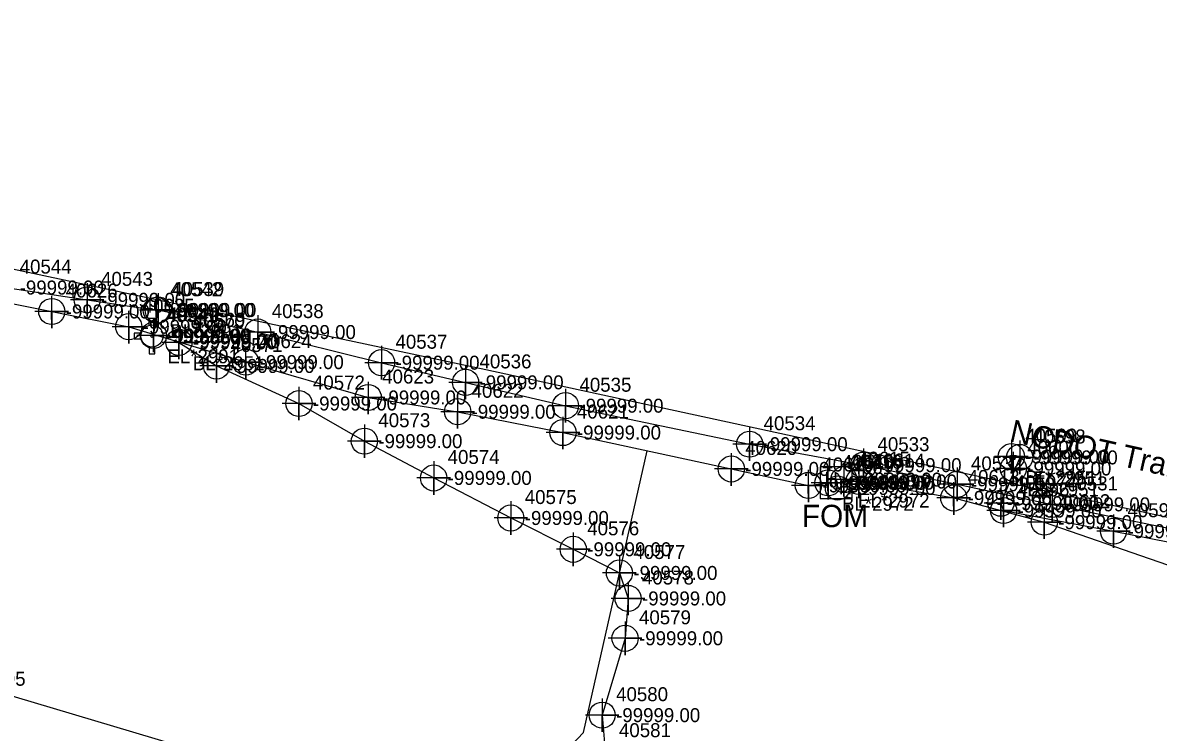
# Model space of a CAD drawing. Extents: x 2083698 to 2094313, y 743246 to 752873.
# Drawn here: x 2091095.5 to 2091298.8, y 744345.3 to 744472.3 of the extents above; entities that cross this region are included whole.
import ezdxf

# ---------------------------------------------------------------- set-up
doc = ezdxf.new("R2010")
doc.units = 0
for name, color, linetype in [('COGO Default Parcel', 7, 'Continuous'), ('COGO Default Point Number', 7, 'Continuous'), ('Exist Property Iron Pin CELL', 7, 'Continuous'), ('Exist Property Iron Pin Cogo Elevation', 7, 'Continuous'), ('Exist Property Iron Pin Cogo Number', 7, 'Continuous'), ('Exist Property Iron Pin Leader', 7, 'Continuous'), ('Exist Property Iron Pin Text', 7, 'Continuous'), ('Exist Property Line', 7, 'Continuous'), ('Exist Property Monument Leader', 7, 'Continuous'), ('Exist Property Monument Text', 7, 'Continuous'), ('Exist Right of Way Easement Line Leader', 7, 'Continuous'), ('Exist Right of Way Easement Line Text', 7, 'Continuous'), ('Exist Right of Way Line', 7, 'Continuous'), ('Exist Right of Way Line Leader', 7, 'Continuous'), ('Exist Right of Way Line Text', 7, 'Continuous'), ('Exist Right of Way Width CELL', 7, 'Continuous'), ('Exist Utilities Other Located Object CELL', 7, 'Continuous'), ('Exist Utilities Other Located Object Text', 7, 'Continuous'), ('Exist Utilities Power Joint Use Telephone Cogo Elevation', 7, 'Continuous'), ('Exist Utilities Power Joint Use Telephone Cogo Number', 7, 'Continuous'), ('Exist Utilities Power UG Cable SUE LOS B', 7, 'Continuous'), ('Exist Utilities Power UG Cable SUE LOS B Text', 7, 'Continuous'), ('Exist Utilities Telephone UG Conduit SUE LOS B', 7, 'Continuous'), ('Exist Utilities Telephone UG Conduit SUE LOS C', 7, 'Continuous'), ('Exist Utilities TV UG Cable SUE LOS C', 7, 'Continuous'), ('Exist Utilities Water UG Line SUE LOS B', 7, 'Continuous'), ('Raster_Level_1', 7, 'Continuous'), ('Scratch_Level_0', 7, 'Continuous'), ('Scratch_Level_2', 7, 'Continuous'), ('Scratch_Level_3', 7, 'Continuous')]:
    doc.layers.add(name, color=color, linetype=linetype)

msp = doc.modelspace()

# ---------------------------------------------------------------- linework, layer by layer
at = {"layer": 'COGO Default Point Number'}
for points in [[(2091107.01, 744425.67), (2091107.01, 744419.67), (2091107.01, 744422.67), (2091110.01, 744422.67), (2091104.01, 744422.67)], [(2091119.4, 744423.81), (2091119.4, 744417.81), (2091119.4, 744420.81), (2091122.4, 744420.81), (2091116.4, 744420.81)], [(2091119.75, 744423.85), (2091119.75, 744417.85), (2091119.75, 744420.85), (2091122.75, 744420.85), (2091116.75, 744420.85)], [(2091137.57, 744419.9), (2091137.57, 744413.9), (2091137.57, 744416.9), (2091140.57, 744416.9), (2091134.57, 744416.9)], [(2091118.88, 744419.31), (2091118.88, 744413.31), (2091118.88, 744416.31), (2091121.88, 744416.31), (2091115.88, 744416.31)], [(2091159.73, 744414.42), (2091159.73, 744408.42), (2091159.73, 744411.42), (2091162.73, 744411.42), (2091156.73, 744411.42)], [(2091174.78, 744410.9), (2091174.78, 744404.9), (2091174.78, 744407.9), (2091177.78, 744407.9), (2091171.78, 744407.9)], [(2091192.68, 744406.72), (2091192.68, 744400.72), (2091192.68, 744403.72), (2091195.68, 744403.72), (2091189.68, 744403.72)], [(2091225.65, 744399.83), (2091225.65, 744393.83), (2091225.65, 744396.83), (2091228.65, 744396.83), (2091222.65, 744396.83)], [(2091246.05, 744396.08), (2091246.05, 744390.08), (2091246.05, 744393.08), (2091249.05, 744393.08), (2091243.05, 744393.08)], [(2091262.79, 744392.65), (2091262.79, 744386.65), (2091262.79, 744389.65), (2091265.79, 744389.65), (2091259.79, 744389.65)], [(2091279.81, 744389.06), (2091279.81, 744383.06), (2091279.81, 744386.06), (2091282.81, 744386.06), (2091276.81, 744386.06)]]:
    msp.add_lwpolyline(points, dxfattribs=at)
for centre in [(2091107.01, 744422.67), (2091119.4, 744420.81), (2091119.75, 744420.85), (2091118.88, 744416.31), (2091137.57, 744416.9), (2091159.73, 744411.42), (2091174.78, 744407.9), (2091192.68, 744403.72), (2091225.65, 744396.83), (2091246.05, 744393.08), (2091262.79, 744389.65), (2091279.81, 744386.06)]:
    msp.add_circle(centre, 2.34, dxfattribs=at)
at = {"layer": 'Exist Property Iron Pin CELL'}
for p, q in [((2091238.28, 744392.8), (2091238.28, 744387.08)), ((2091244, 744392.8), (2091238.28, 744392.8)), ((2091244, 744387.08), (2091244, 744392.8)), ((2091241.14, 744389.94), (2091241.14, 744389.94)), ((2091238.28, 744387.08), (2091244, 744387.08))]:
    msp.add_line(p, q, dxfattribs=at)
at = {"layer": 'Exist Property Iron Pin Text'}
for points in [[(2091123.44, 744418.06), (2091123.44, 744412.06), (2091123.44, 744415.06), (2091126.44, 744415.06), (2091120.44, 744415.06)], [(2091130.19, 744413.83), (2091130.19, 744407.83), (2091130.19, 744410.83), (2091133.19, 744410.83), (2091127.19, 744410.83)], [(2091144.95, 744407.11), (2091144.95, 744401.11), (2091144.95, 744404.11), (2091147.95, 744404.11), (2091141.95, 744404.11)], [(2091156.66, 744400.37), (2091156.66, 744394.37), (2091156.66, 744397.37), (2091159.66, 744397.37), (2091153.66, 744397.37)], [(2091272.52, 744397.61), (2091272.52, 744391.61), (2091272.52, 744394.61), (2091275.52, 744394.61), (2091269.52, 744394.61)], [(2091274.01, 744397.46), (2091274.01, 744391.46), (2091274.01, 744394.46), (2091277.01, 744394.46), (2091271.01, 744394.46)], [(2091272.87, 744395.49), (2091272.87, 744389.49), (2091272.87, 744392.49), (2091275.87, 744392.49), (2091269.87, 744392.49)], [(2091169.07, 744393.79), (2091169.07, 744387.79), (2091169.07, 744390.79), (2091172.07, 744390.79), (2091166.07, 744390.79)], [(2091270.65, 744389.26), (2091270.65, 744383.26), (2091270.65, 744386.26), (2091273.65, 744386.26), (2091267.65, 744386.26)], [(2091271.12, 744387.96), (2091271.12, 744381.96), (2091271.12, 744384.96), (2091274.12, 744384.96), (2091268.12, 744384.96)], [(2091182.88, 744386.62), (2091182.88, 744380.62), (2091182.88, 744383.62), (2091185.88, 744383.62), (2091179.88, 744383.62)], [(2091290.81, 744384.26), (2091290.81, 744378.26), (2091290.81, 744381.26), (2091293.81, 744381.26), (2091287.81, 744381.26)], [(2091194.07, 744381.02), (2091194.07, 744375.02), (2091194.07, 744378.02), (2091197.07, 744378.02), (2091191.07, 744378.02)], [(2091202.33, 744376.78), (2091202.33, 744370.78), (2091202.33, 744373.78), (2091205.33, 744373.78), (2091199.33, 744373.78)], [(2091203.88, 744372.22), (2091203.88, 744366.22), (2091203.88, 744369.22), (2091206.88, 744369.22), (2091200.88, 744369.22)], [(2091203.34, 744365.09), (2091203.34, 744359.09), (2091203.34, 744362.09), (2091206.34, 744362.09), (2091200.34, 744362.09)], [(2091199.24, 744351.33), (2091199.24, 744345.33), (2091199.24, 744348.33), (2091202.24, 744348.33), (2091196.24, 744348.33)]]:
    msp.add_lwpolyline(points, dxfattribs=at)
for centre in [(2091123.44, 744415.06), (2091130.19, 744410.83), (2091144.95, 744404.11), (2091156.66, 744397.37), (2091272.52, 744394.61), (2091274.01, 744394.46), (2091169.07, 744390.79), (2091272.87, 744392.49), (2091270.65, 744386.26), (2091271.12, 744384.96), (2091182.88, 744383.62), (2091290.81, 744381.26), (2091194.07, 744378.02), (2091202.33, 744373.78), (2091203.88, 744369.22), (2091203.34, 744362.09), (2091199.24, 744348.33)]:
    msp.add_circle(centre, 2.34, dxfattribs=at)
at = {"layer": 'Exist Right of Way Line Text'}
for points in [[(2091100.63, 744423.4), (2091100.67, 744417.58), (2091100.65, 744420.58), (2091103.67, 744420.58), (2091097.67, 744420.58)], [(2091114.43, 744420.67), (2091114.47, 744414.86), (2091114.45, 744417.86), (2091117.47, 744417.86), (2091111.47, 744417.86)], [(2091135.38, 744414.33), (2091135.41, 744408.52), (2091135.4, 744411.52), (2091138.41, 744411.52), (2091132.41, 744411.52)], [(2091157.32, 744408), (2091157.35, 744402.19), (2091157.33, 744405.19), (2091160.35, 744405.19), (2091154.35, 744405.19)], [(2091173.33, 744405.45), (2091173.36, 744399.64), (2091173.34, 744402.64), (2091176.36, 744402.64), (2091170.36, 744402.64)], [(2091192.19, 744401.72), (2091192.22, 744395.91), (2091192.2, 744398.91), (2091195.22, 744398.91), (2091189.22, 744398.91)], [(2091222.34, 744395.21), (2091222.37, 744389.4), (2091222.36, 744392.4), (2091225.37, 744392.4), (2091219.37, 744392.4)], [(2091242.51, 744393.31), (2091242.54, 744387.49), (2091242.52, 744390.49), (2091245.54, 744390.49), (2091239.54, 744390.49)], [(2091245.18, 744392.96), (2091245.22, 744387.15), (2091245.2, 744390.15), (2091248.22, 744390.15), (2091242.22, 744390.15)], [(2091236.14, 744392.26), (2091236.17, 744386.45), (2091236.15, 744389.45), (2091239.17, 744389.45), (2091233.17, 744389.45)], [(2091239.65, 744392.73), (2091239.69, 744386.91), (2091239.67, 744389.91), (2091242.69, 744389.91), (2091236.69, 744389.91)], [(2091262.17, 744390.03), (2091262.2, 744384.21), (2091262.18, 744387.21), (2091265.2, 744387.21), (2091259.2, 744387.21)], [(2091278.39, 744385.69), (2091278.42, 744379.87), (2091278.41, 744382.87), (2091281.42, 744382.87), (2091275.42, 744382.87)]]:
    msp.add_lwpolyline(points, dxfattribs=at)
for centre in [(2091100.67, 744420.58), (2091114.47, 744417.86), (2091135.41, 744411.52), (2091157.35, 744405.19), (2091173.36, 744402.64), (2091192.22, 744398.91), (2091222.37, 744392.4), (2091236.17, 744389.45), (2091239.69, 744389.91), (2091242.54, 744390.49), (2091245.22, 744390.15), (2091262.2, 744387.21), (2091278.42, 744382.87)]:
    msp.add_circle(centre, 2.34, dxfattribs=at)
at = {"layer": 'Exist Utilities Other Located Object CELL'}
for radius in [2.18, 0.24]:
    msp.add_circle((2091241.39, 744388.99), radius, dxfattribs=at)
at = {"layer": 'Exist Utilities Power UG Cable SUE LOS B'}
msp.add_line((2091272.52, 744394.61), (2091272.87, 744392.49), dxfattribs=at)
for points in [[(2091123.44, 744415.06), (2091130.19, 744410.83), (2091144.95, 744404.11), (2091156.66, 744397.37), (2091169.07, 744390.79), (2091182.88, 744383.62), (2091194.07, 744378.02), (2091202.33, 744373.78), (2091203.88, 744369.22), (2091203.34, 744362.09), (2091199.24, 744348.33), (2091199.75, 744341.89), (2091203.94, 744334.56), (2091208.76, 744334.42), (2091211.38, 744336.87)], [(2091274.01, 744394.46), (2091270.65, 744386.26), (2091271.12, 744384.96), (2091290.81, 744381.26), (2091304.17, 744378.63), (2091324.7, 744374.67), (2091337.06, 744369.57), (2091348.22, 744363.92), (2091350.33, 744362.88)]]:
    msp.add_lwpolyline(points, dxfattribs=at)
at = {"layer": 'Exist Utilities Telephone UG Conduit SUE LOS B'}
for points in [[(2090890.56, 744469.77), (2090897.36, 744470.03), (2090919.19, 744460.85), (2090939.78, 744455.97), (2090957.49, 744454.33), (2090977.44, 744448.69), (2090996.96, 744442.97), (2091015.78, 744439.38), (2091033.71, 744434.32), (2091057.15, 744429.17), (2091077.11, 744425.28), (2091100.67, 744420.58), (2091114.47, 744417.86), (2091135.41, 744411.52), (2091157.35, 744405.19), (2091173.36, 744402.64), (2091192.22, 744398.91), (2091222.37, 744392.4), (2091236.17, 744389.45), (2091239.69, 744389.91)], [(2090806.91, 744430.84), (2090828.12, 744425.56), (2090875.81, 744412.95), (2090912.62, 744403.8), (2090953.84, 744392.46), (2090996.45, 744380.46), (2091034.29, 744369.44), (2091083.26, 744354.84), (2091136.72, 744338.88), (2091178.24, 744327.59), (2091220.24, 744315.64), (2091261.35, 744302.25), (2091279.18, 744292.69), (2091315.02, 744278.76)], [(2091242.54, 744390.49), (2091245.22, 744390.15), (2091262.2, 744387.21), (2091278.42, 744382.87), (2091303.56, 744374.19), (2091323.58, 744368.52), (2091346.95, 744365.26), (2091375.52, 744357.7), (2091401.28, 744349.84), (2091424.1, 744344.64), (2091445.92, 744340.4), (2091465.61, 744335.98), (2091473.85, 744334.83), (2091473.86, 744334.82), (2091479.86, 744333.66)]]:
    msp.add_lwpolyline(points, dxfattribs=at)
at = {"layer": 'Exist Utilities Telephone UG Conduit SUE LOS C'}
msp.add_lwpolyline([(2091183.95, 744332.62), (2091195.91, 744345.2), (2091207.3, 744395.65)], dxfattribs=at)
at = {"layer": 'Exist Utilities TV UG Cable SUE LOS C'}
msp.add_lwpolyline([(2091054.67, 744436.34), (2091073.65, 744432.47), (2091178.42, 744410.18), (2091400.3, 744362.19), (2091479.76, 744342.26), (2091533.68, 744324.76), (2091743.8, 744269.35), (2091786.22, 744260.43)], dxfattribs=at)
at = {"layer": 'Exist Utilities Water UG Line SUE LOS B'}
for points in [[(2090757, 744489.94), (2090781.29, 744488.85), (2090797.98, 744487.59), (2090827.47, 744482.42), (2090838.65, 744479.65), (2090852.58, 744478.98), (2090873.77, 744477.12), (2090883.51, 744476.24), (2090899.92, 744472.35), (2090921.56, 744466.76), (2090941.24, 744461.84), (2090958.11, 744457.6), (2090978.69, 744451.85), (2090998.25, 744447.07), (2091015.68, 744441.91), (2091033.15, 744437.09), (2091043.48, 744435.09), (2091058.27, 744432.2), (2091077.37, 744428.05), (2091092.43, 744424.87), (2091107.01, 744422.67), (2091119.4, 744420.81)], [(2091118.88, 744416.31), (2091119.75, 744420.85)], [(2091119.75, 744420.85), (2091137.57, 744416.9), (2091159.73, 744411.42), (2091174.78, 744407.9), (2091192.68, 744403.72), (2091225.65, 744396.83), (2091246.05, 744393.08), (2091262.79, 744389.65), (2091279.81, 744386.06), (2091324.78, 744376.93), (2091324.75, 744376.92), (2091377.96, 744364.84), (2091402.77, 744359.19), (2091425.76, 744353.62), (2091447.37, 744348.1), (2091466.41, 744343.18), (2091483.9, 744339.28), (2091501.85, 744335.1), (2091516.05, 744331.54), (2091527.86, 744328.96), (2091537.96, 744326.53)]]:
    msp.add_lwpolyline(points, dxfattribs=at)
at = {"layer": 'Raster_Level_1'}
msp.add_line((2091118.62, 744416.19), (2091118.62, 744416.19), dxfattribs=at)
for points in [[(2091118.11, 744418.11), (2091118.11, 744419.39), (2091119.14, 744419.39), (2091119.14, 744418.08)], [(2091116.71, 744416.71), (2091115.43, 744416.71), (2091115.43, 744415.68), (2091116.71, 744415.68)], [(2091118.11, 744414.28), (2091118.11, 744412.99), (2091119.14, 744412.99), (2091119.14, 744414.31)]]:
    msp.add_lwpolyline(points, dxfattribs=at)
for radius in [1.98, 0.243]:
    msp.add_circle((2091118.62, 744416.19), radius, dxfattribs=at)

# ---------------------------------------------------------------- texts
at = {"layer": 'COGO Default Parcel'}
msp.add_text('40617', height=2.5, dxfattribs=at).set_placement((2091243.89, 744391.49))
at = {"layer": 'Exist Property Iron Pin CELL'}
for p in [(2091239.06, 744389.35), (2091241.63, 744387.88)]:
    msp.add_text('H', height=2.5, dxfattribs=at).set_placement(p)
at = {"layer": 'Exist Property Iron Pin Cogo Elevation'}
msp.add_text('-99999.00', height=2.5, dxfattribs=at).set_placement((2091243.64, 744388.69))
at = {"layer": 'Exist Property Iron Pin Cogo Number'}
msp.add_text('40616', height=2.5, dxfattribs=at).set_placement((2091243.64, 744392.44))
at = {"layer": 'Exist Property Iron Pin Leader'}
for s, p in [('40570', (2091125.94, 744417.56)), ('40571', (2091132.69, 744413.33)), ('40572', (2091147.45, 744406.61)), ('40573', (2091159.16, 744399.87)), ('40599', (2091275.02, 744397.11)), ('40598', (2091276.51, 744396.96)), ('40600', (2091275.37, 744394.99)), ('40574', (2091171.57, 744393.29)), ('40597', (2091273.15, 744388.76)), ('40596', (2091273.62, 744387.46)), ('40575', (2091185.38, 744386.12)), ('40595', (2091293.31, 744383.76)), ('40576', (2091196.57, 744380.52)), ('40577', (2091204.83, 744376.28)), ('40578', (2091206.38, 744371.72)), ('40579', (2091205.84, 744364.59)), ('40580', (2091201.74, 744350.83)), ('40581', (2091202.25, 744344.39))]:
    msp.add_text(s, height=2.5, dxfattribs=at).set_placement(p)
at = {"layer": 'Exist Property Line'}
for p in [(2091094.93, 744423.62), (2091109.51, 744421.42), (2091121.9, 744419.56), (2091122.25, 744419.6), (2091121.38, 744415.06), (2091140.07, 744415.65), (2091162.23, 744410.17), (2091177.28, 744406.65), (2091195.18, 744402.47), (2091228.15, 744395.58), (2091248.55, 744391.83), (2091265.29, 744388.4), (2091282.31, 744384.81)]:
    msp.add_text('-99999.00', height=2.5, dxfattribs=at).set_placement(p)
at = {"layer": 'Exist Property Monument Leader'}
for s, p in [('BL*2951', (2091125.94, 744410.06)), ('BL*2951', (2091275.02, 744389.61)), ('EL*2951', (2091276.51, 744389.46)), ('EL*2951', (2091275.37, 744387.49))]:
    msp.add_text(s, height=2.5, dxfattribs=at).set_placement(p)
at = {"layer": 'Exist Property Monument Text'}
for p in [(2091125.94, 744413.81), (2091132.69, 744409.58), (2091147.45, 744402.86), (2091159.16, 744396.12), (2091275.02, 744393.36), (2091276.51, 744393.21), (2091275.37, 744391.24), (2091171.57, 744389.54), (2091273.15, 744385.01), (2091185.38, 744382.37), (2091273.62, 744383.71), (2091293.31, 744380.01), (2091196.57, 744376.77), (2091204.83, 744372.53), (2091206.38, 744367.97), (2091205.84, 744360.84), (2091201.74, 744347.08)]:
    msp.add_text('-99999.00', height=2.5, dxfattribs=at).set_placement(p)
at = {"layer": 'Exist Right of Way Easement Line Leader'}
msp.add_text('-99999.00', height=2.5, dxfattribs=at).set_placement((2091121.12, 744414.94))
at = {"layer": 'Exist Right of Way Easement Line Text'}
msp.add_text('40541', height=2.5, dxfattribs=at).set_placement((2091121.12, 744418.69))
at = {"layer": 'Exist Right of Way Line'}
for s, p in [('40544', (2091094.93, 744427.37)), ('40543', (2091109.51, 744425.17)), ('40542', (2091121.9, 744423.31)), ('40539', (2091122.25, 744423.35)), ('40540', (2091121.38, 744418.81)), ('40538', (2091140.07, 744419.4)), ('40537', (2091162.23, 744413.92)), ('40536', (2091177.28, 744410.4)), ('40535', (2091195.18, 744406.22)), ('40534', (2091228.15, 744399.33)), ('40533', (2091248.55, 744395.58)), ('40532', (2091265.29, 744392.15)), ('40531', (2091282.31, 744388.56))]:
    msp.add_text(s, height=2.5, dxfattribs=at).set_placement(p)
at = {"layer": 'Exist Right of Way Line Leader'}
for s, p in [('40626', (2091103.17, 744423.08)), ('40625', (2091116.97, 744420.36)), ('40624', (2091137.91, 744414.02)), ('40623', (2091159.85, 744407.69)), ('40622', (2091175.86, 744405.14)), ('40621', (2091194.72, 744401.41)), ('40620', (2091224.87, 744394.9)), ('40618', (2091242.19, 744392.41)), ('40615', (2091245.04, 744392.99)), ('40614', (2091247.72, 744392.65)), ('40619', (2091238.67, 744391.95)), ('40613', (2091264.7, 744389.71)), ('40612', (2091280.92, 744385.37))]:
    msp.add_text(s, height=2.5, dxfattribs=at).set_placement(p)
at = {"layer": 'Exist Right of Way Width CELL'}
for s, p in [('BL*2991', (2091121.9, 744415.81)), ('EL*2991', (2091121.38, 744411.31))]:
    msp.add_text(s, height=2.5, dxfattribs=at).set_placement(p)
at = {"layer": 'Exist Utilities Other Located Object Text'}
msp.add_text('FOM', height=4, dxfattribs=at).set_placement((2091234.99, 744381.98))
at = {"layer": 'Exist Utilities Power Joint Use Telephone Cogo Elevation'}
msp.add_text('-99999.00', height=2.5, dxfattribs=at).set_placement((2091126.05, 744414.09))
at = {"layer": 'Exist Utilities Power Joint Use Telephone Cogo Number'}
msp.add_text('40569', height=2.5, dxfattribs=at).set_placement((2091126.05, 744417.84))
at = {"layer": 'Exist Utilities Power UG Cable SUE LOS B Text'}
msp.add_text('NCDOT Traffic Control', height=4, rotation=347.4649, dxfattribs=at).set_placement((2091272.02, 744397.38))
at = {"layer": 'Scratch_Level_0'}
msp.add_text('-99999.00', height=2.5, dxfattribs=at).set_placement((2091243.89, 744387.74))
at = {"layer": 'Scratch_Level_2'}
for s, p in [('-99999.00', (2091103.17, 744419.33)), ('-99999.00', (2091116.97, 744416.61)), ('-99999.00', (2091137.91, 744410.27)), ('-99999.00', (2091159.85, 744403.94)), ('-99999.00', (2091175.86, 744401.39)), ('-99999.00', (2091194.72, 744397.66)), ('-99999.00', (2091224.87, 744391.15)), ('-99999.00', (2091242.19, 744388.66)), ('-99999.00', (2091245.04, 744389.24)), ('-99999.00', (2091247.72, 744388.9)), ('-99999.00', (2091238.67, 744388.2)), ('-99999.00', (2091264.7, 744385.96)), ('-99999.00', (2091280.92, 744381.62)), ('446.95', (2091085.76, 744353.59))]:
    msp.add_text(s, height=2.5, dxfattribs=at).set_placement(p)
at = {"layer": 'Scratch_Level_3'}
for s, p in [('BL*2972', (2091242.19, 744384.91)), ('EL*2972', (2091245.04, 744385.49))]:
    msp.add_text(s, height=2.5, dxfattribs=at).set_placement(p)

doc.saveas('drawing.dxf')
